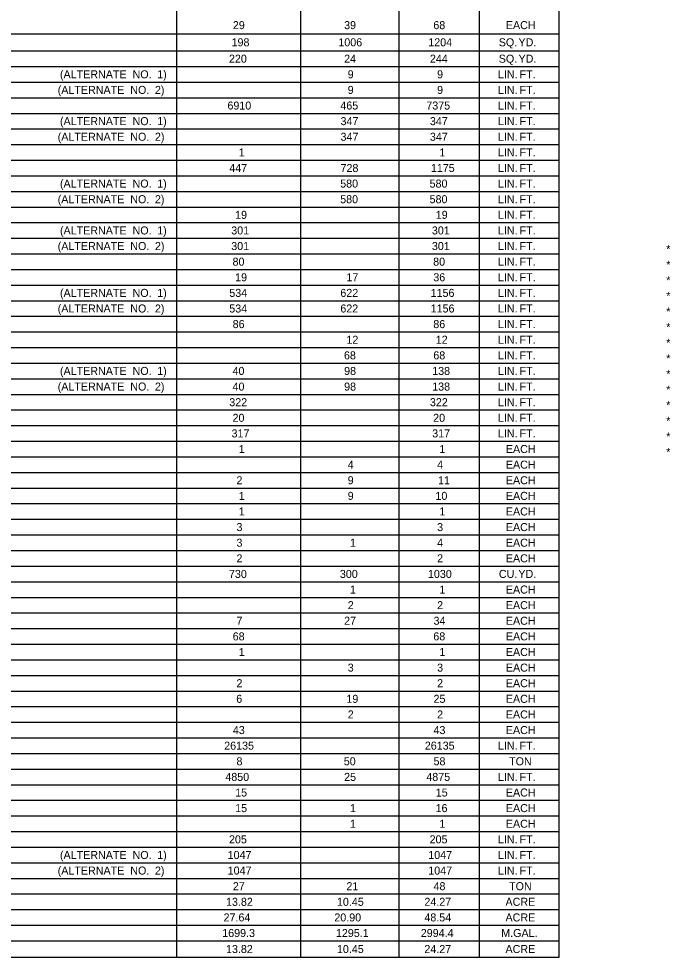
# Model space of a CAD drawing. Extents: x 1226603 to 1228117, y 151305 to 152343.
# Drawn here: x 1226948.8 to 1227294.6, y 151339 to 151837.1 of the extents above; entities that cross this region are included whole.
import ezdxf

# ---------------------------------------------------------------- set-up
doc = ezdxf.new("R2010")
doc.units = 0
doc.layers.add('R_Dimension', color=7, linetype='Continuous')

msp = doc.modelspace()

# ---------------------------------------------------------------- linework, layer by layer
at = {"layer": 'R_Dimension'}
for p, q in [((1227032.58, 151338.98), (1227032.58, 152334.72)), ((1227235.63, 151338.98), (1227235.63, 152334.72)), ((1227098.47, 151338.98), (1227098.47, 152320.63)), ((1227150.68, 151338.98), (1227150.68, 152320.63)), ((1227193.36, 151338.98), (1227193.36, 152320.63)), ((1226605.78, 151829.18), (1227235.63, 151829.18)), ((1226605.78, 151820.06), (1227235.63, 151820.06)), ((1226605.78, 151811.78), (1227235.63, 151811.78)), ((1226605.78, 151803.49), (1227235.63, 151803.49)), ((1226605.78, 151795.2), (1227235.63, 151795.2)), ((1226605.78, 151786.91), (1227235.63, 151786.91)), ((1226605.78, 151778.63), (1227235.63, 151778.63)), ((1226605.78, 151770.34), (1227235.63, 151770.34)), ((1226605.78, 151762.05), (1227235.63, 151762.05)), ((1226605.78, 151753.76), (1227235.63, 151753.76)), ((1226605.78, 151745.48), (1227235.63, 151745.48)), ((1226605.78, 151737.19), (1227235.63, 151737.19)), ((1226605.78, 151728.9), (1227235.63, 151728.9)), ((1226605.78, 151720.61), (1227235.63, 151720.61)), ((1226605.78, 151712.33), (1227235.63, 151712.33)), ((1226605.78, 151704.04), (1227235.63, 151704.04)), ((1226605.78, 151695.75), (1227235.63, 151695.75)), ((1226605.78, 151687.46), (1227235.63, 151687.46)), ((1226605.78, 151679.18), (1227235.63, 151679.18)), ((1226605.78, 151670.89), (1227235.63, 151670.89)), ((1226605.78, 151662.6), (1227235.63, 151662.6)), ((1226605.78, 151654.31), (1227235.63, 151654.31)), ((1226605.78, 151646.03), (1227235.63, 151646.03)), ((1226605.78, 151637.74), (1227235.63, 151637.74)), ((1226605.78, 151629.45), (1227235.63, 151629.45)), ((1226605.78, 151621.16), (1227235.63, 151621.16)), ((1226605.78, 151612.88), (1227235.63, 151612.88)), ((1226605.78, 151604.59), (1227235.63, 151604.59)), ((1226605.78, 151596.3), (1227235.63, 151596.3)), ((1226605.78, 151588.01), (1227235.63, 151588.01)), ((1226605.78, 151579.73), (1227235.63, 151579.73)), ((1226605.78, 151571.44), (1227235.63, 151571.44)), ((1226605.78, 151563.15), (1227235.63, 151563.15)), ((1226605.78, 151554.86), (1227235.63, 151554.86)), ((1226605.78, 151546.58), (1227235.63, 151546.58)), ((1226605.78, 151538.29), (1227235.63, 151538.29)), ((1226605.78, 151530), (1227235.63, 151530)), ((1226605.78, 151521.71), (1227235.63, 151521.71)), ((1226605.78, 151513.43), (1227235.63, 151513.43)), ((1226605.78, 151505.14), (1227235.63, 151505.14)), ((1226605.78, 151496.85), (1227235.63, 151496.85)), ((1226605.78, 151488.56), (1227235.63, 151488.56)), ((1226605.78, 151480.28), (1227235.63, 151480.28)), ((1226605.78, 151471.99), (1227235.63, 151471.99)), ((1226605.78, 151463.7), (1227235.63, 151463.7)), ((1226605.78, 151455.41), (1227235.63, 151455.41)), ((1226605.78, 151447.13), (1227235.63, 151447.13)), ((1226605.78, 151438.84), (1227235.63, 151438.84)), ((1226605.78, 151430.55), (1227235.63, 151430.55)), ((1226605.78, 151422.26), (1227235.63, 151422.26)), ((1226605.78, 151413.98), (1227235.63, 151413.98)), ((1226605.78, 151405.69), (1227235.63, 151405.69)), ((1226605.78, 151397.4), (1227235.63, 151397.4)), ((1226605.78, 151389.11), (1227235.63, 151389.11)), ((1226605.78, 151380.83), (1227235.63, 151380.83)), ((1226605.78, 151372.54), (1227235.63, 151372.54)), ((1226605.78, 151364.25), (1227235.63, 151364.25)), ((1226605.78, 151355.96), (1227235.63, 151355.96)), ((1226605.78, 151347.68), (1227235.63, 151347.68)), ((1226605.78, 151338.98), (1227235.63, 151338.98))]:
    msp.add_line(p, q, dxfattribs=at)

# ---------------------------------------------------------------- texts
for s, p in [('29', (1227062.4, 151831.61)), ('39', (1227121.45, 151831.61)), ('68', (1227168.81, 151831.61)), ('EACH', (1227207.3, 151831.61)), ('198', (1227061.71, 151822.5)), ('1006', (1227118.4, 151822.5)), ('1204', (1227166.13, 151822.5)), ('SQ.', (1227203.53, 151822.5)), (' YD.', (1227212.44, 151822.5)), ('220', (1227060.32, 151813.8)), ('24', (1227121.46, 151813.8)), ('244', (1227167, 151813.8)), ('SQ.', (1227203.53, 151813.8)), (' YD.', (1227212.44, 151813.8)), ('(ALTERNATE', (1226970.63, 151805.51)), (' NO.', (1227007.58, 151805.51)), (' 1)', (1227020.66, 151805.51)), ('9', (1227123.35, 151805.51)), ('9', (1227170.8, 151805.51)), ('LIN.', (1227203.1, 151805.51)), (' FT.', (1227213, 151805.51)), ('(ALTERNATE', (1226969.43, 151797.22)), (' NO.', (1227006.37, 151797.22)), (' 2)', (1227019.46, 151797.22)), ('9', (1227123.35, 151797.22)), ('9', (1227170.8, 151797.22)), ('LIN.', (1227203.1, 151797.22)), (' FT.', (1227213, 151797.22)), ('6910', (1227059.52, 151788.93)), ('465', (1227119.45, 151788.93)), ('7375', (1227165.09, 151788.93)), ('LIN.', (1227203.1, 151788.93)), (' FT.', (1227213, 151788.93)), ('(ALTERNATE', (1226970.63, 151780.65)), (' NO.', (1227007.58, 151780.65)), (' 1)', (1227020.66, 151780.65)), ('347', (1227119.55, 151780.65)), ('347', (1227167, 151780.65)), ('LIN.', (1227203.1, 151780.65)), (' FT.', (1227213, 151780.65)), ('(ALTERNATE', (1226969.43, 151772.36)), (' NO.', (1227006.37, 151772.36)), (' 2)', (1227019.46, 151772.36)), ('347', (1227119.55, 151772.36)), ('347', (1227167, 151772.36)), ('LIN.', (1227203.1, 151772.36)), (' FT.', (1227213, 151772.36)), ('1', (1227065.53, 151764.07)), ('1', (1227172.02, 151764.07)), ('LIN.', (1227203.1, 151764.07)), (' FT.', (1227213, 151764.07)), ('447', (1227060.51, 151755.78)), ('728', (1227119.55, 151755.78)), ('1175', (1227167.5, 151755.78)), ('LIN.', (1227203.1, 151755.78)), (' FT.', (1227213, 151755.78)), ('(ALTERNATE', (1226970.63, 151747.5)), (' NO.', (1227007.58, 151747.5)), (' 1)', (1227020.66, 151747.5)), ('580', (1227119.37, 151747.5)), ('580', (1227166.82, 151747.5)), ('LIN.', (1227203.1, 151747.5)), (' FT.', (1227213, 151747.5)), ('(ALTERNATE', (1226969.43, 151739.21)), (' NO.', (1227006.37, 151739.21)), (' 2)', (1227019.46, 151739.21)), ('580', (1227119.37, 151739.21)), ('580', (1227166.82, 151739.21)), ('LIN.', (1227203.1, 151739.21)), (' FT.', (1227213, 151739.21)), ('19', (1227063.6, 151730.92)), ('19', (1227170.1, 151730.92)), ('LIN.', (1227203.1, 151730.92)), (' FT.', (1227213, 151730.92)), ('(ALTERNATE', (1226970.63, 151722.63)), (' NO.', (1227007.58, 151722.63)), (' 1)', (1227020.66, 151722.63)), ('301', (1227061.54, 151722.63)), ('301', (1227168.04, 151722.63)), ('LIN.', (1227203.1, 151722.63)), (' FT.', (1227213, 151722.63)), ('(ALTERNATE', (1226969.43, 151714.35)), (' NO.', (1227006.37, 151714.35)), (' 2)', (1227019.46, 151714.35)), ('301', (1227061.54, 151714.35)), ('301', (1227168.04, 151714.35)), ('LIN.', (1227203.1, 151714.35)), (' FT.', (1227213, 151714.35)), ('*', (1227292.43, 151712.76)), ('80', (1227062.23, 151706.06)), ('80', (1227168.72, 151706.06)), ('LIN.', (1227203.1, 151706.06)), (' FT.', (1227213, 151706.06)), ('*', (1227292.43, 151704.48)), ('19', (1227063.6, 151697.77)), ('17', (1227122.67, 151697.77)), ('36', (1227168.79, 151697.77)), ('LIN.', (1227203.1, 151697.77)), (' FT.', (1227213, 151697.77)), ('*', (1227292.43, 151696.19)), ('(ALTERNATE', (1226970.63, 151689.48)), (' NO.', (1227007.58, 151689.48)), (' 1)', (1227020.66, 151689.48)), ('534', (1227060.51, 151689.48)), ('622', (1227119.45, 151689.48)), ('1156', (1227167.39, 151689.48)), ('LIN.', (1227203.1, 151689.48)), (' FT.', (1227213, 151689.48)), ('*', (1227292.43, 151687.9)), ('(ALTERNATE', (1226969.43, 151681.2)), (' NO.', (1227006.37, 151681.2)), (' 2)', (1227019.46, 151681.2)), ('534', (1227060.51, 151681.2)), ('622', (1227119.45, 151681.2)), ('1156', (1227167.39, 151681.2)), ('LIN.', (1227203.1, 151681.2)), (' FT.', (1227213, 151681.2)), ('*', (1227292.43, 151679.61)), ('86', (1227062.3, 151672.91)), ('86', (1227168.79, 151672.91)), ('LIN.', (1227203.1, 151672.91)), (' FT.', (1227213, 151672.91)), ('*', (1227292.43, 151671.33)), ('12', (1227122.67, 151664.62)), ('12', (1227170.11, 151664.62)), ('LIN.', (1227203.1, 151664.62)), (' FT.', (1227213, 151664.62)), ('*', (1227292.43, 151663.04)), ('68', (1227121.36, 151656.33)), ('68', (1227168.81, 151656.33)), ('LIN.', (1227203.1, 151656.33)), (' FT.', (1227213, 151656.33)), ('*', (1227292.43, 151654.75)), ('(ALTERNATE', (1226970.63, 151648.05)), (' NO.', (1227007.58, 151648.05)), (' 1)', (1227020.66, 151648.05)), ('40', (1227062.23, 151648.05)), ('98', (1227121.46, 151648.05)), ('138', (1227168.21, 151648.05)), ('LIN.', (1227203.1, 151648.05)), (' FT.', (1227213, 151648.05)), ('*', (1227292.43, 151646.46)), ('(ALTERNATE', (1226969.43, 151639.76)), (' NO.', (1227006.37, 151639.76)), (' 2)', (1227019.46, 151639.76)), ('40', (1227062.23, 151639.76)), ('98', (1227121.46, 151639.76)), ('138', (1227168.21, 151639.76)), ('LIN.', (1227203.1, 151639.76)), (' FT.', (1227213, 151639.76)), ('*', (1227292.43, 151638.18)), ('322', (1227060.51, 151631.47)), ('322', (1227167, 151631.47)), ('LIN.', (1227203.1, 151631.47)), (' FT.', (1227213, 151631.47)), ('*', (1227292.43, 151629.89)), ('20', (1227062.23, 151623.18)), ('20', (1227168.72, 151623.18)), ('LIN.', (1227203.1, 151623.18)), (' FT.', (1227213, 151623.18)), ('*', (1227292.43, 151621.6)), ('317', (1227061.71, 151614.9)), ('317', (1227168.21, 151614.9)), ('LIN.', (1227203.1, 151614.9)), (' FT.', (1227213, 151614.9)), ('*', (1227292.43, 151613.31)), ('1', (1227065.53, 151606.61)), ('1', (1227172.02, 151606.61)), ('EACH', (1227207.3, 151606.61)), ('*', (1227292.43, 151605.03)), ('4', (1227123.37, 151598.32)), ('4', (1227170.82, 151598.32)), ('EACH', (1227207.3, 151598.32)), ('2', (1227064.32, 151590.03)), ('9', (1227123.35, 151590.03)), ('11', (1227171.32, 151590.03)), ('EACH', (1227207.3, 151590.03)), ('1', (1227065.53, 151581.75)), ('9', (1227123.35, 151581.75)), ('10', (1227169.93, 151581.75)), ('EACH', (1227207.3, 151581.75)), ('1', (1227065.53, 151573.46)), ('1', (1227172.02, 151573.46)), ('EACH', (1227207.3, 151573.46)), ('3', (1227064.32, 151565.17)), ('3', (1227170.82, 151565.17)), ('EACH', (1227207.3, 151565.17)), ('3', (1227064.32, 151556.88)), ('1', (1227124.57, 151556.88)), ('4', (1227170.82, 151556.88)), ('EACH', (1227207.3, 151556.88)), ('2', (1227064.32, 151548.6)), ('2', (1227170.82, 151548.6)), ('EACH', (1227207.3, 151548.6)), ('730', (1227060.32, 151540.31)), ('300', (1227119.2, 151540.31)), ('1030', (1227165.95, 151540.31)), ('CU.', (1227203.6, 151540.31)), (' YD.', (1227212.37, 151540.31)), ('1', (1227124.57, 151532.02)), ('1', (1227172.02, 151532.02)), ('EACH', (1227207.3, 151532.02)), ('2', (1227123.37, 151523.73)), ('2', (1227170.82, 151523.73)), ('EACH', (1227207.3, 151523.73)), ('7', (1227064.32, 151515.45)), ('27', (1227121.46, 151515.45)), ('34', (1227168.91, 151515.45)), ('EACH', (1227207.3, 151515.45)), ('68', (1227062.31, 151507.16)), ('68', (1227168.81, 151507.16)), ('EACH', (1227207.3, 151507.16)), ('1', (1227065.53, 151498.87)), ('1', (1227172.02, 151498.87)), ('EACH', (1227207.3, 151498.87)), ('3', (1227123.37, 151490.58)), ('3', (1227170.82, 151490.58)), ('EACH', (1227207.3, 151490.58)), ('2', (1227064.32, 151482.3)), ('2', (1227170.82, 151482.3)), ('EACH', (1227207.3, 151482.3)), ('6', (1227064.2, 151474.01)), ('19', (1227122.65, 151474.01)), ('25', (1227168.91, 151474.01)), ('EACH', (1227207.3, 151474.01)), ('2', (1227123.37, 151465.72)), ('2', (1227170.82, 151465.72)), ('EACH', (1227207.3, 151465.72)), ('43', (1227062.41, 151457.43)), ('43', (1227168.91, 151457.43)), ('EACH', (1227207.3, 151457.43)), ('26135', (1227057.8, 151449.15)), ('26135', (1227164.29, 151449.15)), ('LIN.', (1227203.1, 151449.15)), (' FT.', (1227213, 151449.15)), ('8', (1227064.32, 151440.86)), ('50', (1227121.28, 151440.86)), ('58', (1227168.91, 151440.86)), ('TON', (1227209.02, 151440.86)), ('4850', (1227058.41, 151432.57)), ('25', (1227121.46, 151432.57)), ('4875', (1227165.09, 151432.57)), ('LIN.', (1227203.1, 151432.57)), (' FT.', (1227213, 151432.57)), ('15', (1227063.62, 151424.28)), ('15', (1227170.11, 151424.28)), ('EACH', (1227207.3, 151424.28)), ('15', (1227063.62, 151416)), ('1', (1227124.57, 151416)), ('16', (1227170, 151416)), ('EACH', (1227207.3, 151416)), ('1', (1227124.57, 151407.71)), ('1', (1227172.02, 151407.71)), ('EACH', (1227207.3, 151407.71)), ('205', (1227060.34, 151399.42)), ('205', (1227166.83, 151399.42)), ('LIN.', (1227203.1, 151399.42)), (' FT.', (1227213, 151399.42)), ('(ALTERNATE', (1226970.63, 151391.13)), (' NO.', (1227007.58, 151391.13)), (' 1)', (1227020.66, 151391.13)), ('1047', (1227059.64, 151391.13)), ('1047', (1227166.13, 151391.13)), ('LIN.', (1227203.1, 151391.13)), (' FT.', (1227213, 151391.13)), ('(ALTERNATE', (1226969.43, 151382.85)), (' NO.', (1227006.37, 151382.85)), (' 2)', (1227019.46, 151382.85)), ('1047', (1227059.64, 151382.85)), ('1047', (1227166.13, 151382.85)), ('LIN.', (1227203.1, 151382.85)), (' FT.', (1227213, 151382.85)), ('27', (1227062.41, 151374.56)), ('21', (1227122.67, 151374.56)), ('48', (1227168.91, 151374.56)), ('TON', (1227209.02, 151374.56)), ('13.82', (1227058.77, 151366.27)), ('10.45', (1227117.65, 151366.27)), ('24.27', (1227164.06, 151366.27)), ('ACRE', (1227207.1, 151366.27)), ('27.64', (1227057.46, 151357.98)), ('20.90', (1227116.26, 151357.98)), ('48.54', (1227164.06, 151357.98)), ('ACRE', (1227207.1, 151357.98)), ('1699.3', (1227056.76, 151349.7)), ('1295.1', (1227117.11, 151349.7)), ('2994.4', (1227162.15, 151349.7)), ('M.GAL.', (1227204.86, 151349.7)), ('13.82', (1227058.77, 151341.2)), ('10.45', (1227117.65, 151341.2)), ('24.27', (1227164.06, 151341.2)), ('ACRE', (1227207.1, 151341.2))]:
    msp.add_text(s, height=4.25, dxfattribs=at).set_placement(p)

doc.saveas('drawing.dxf')
